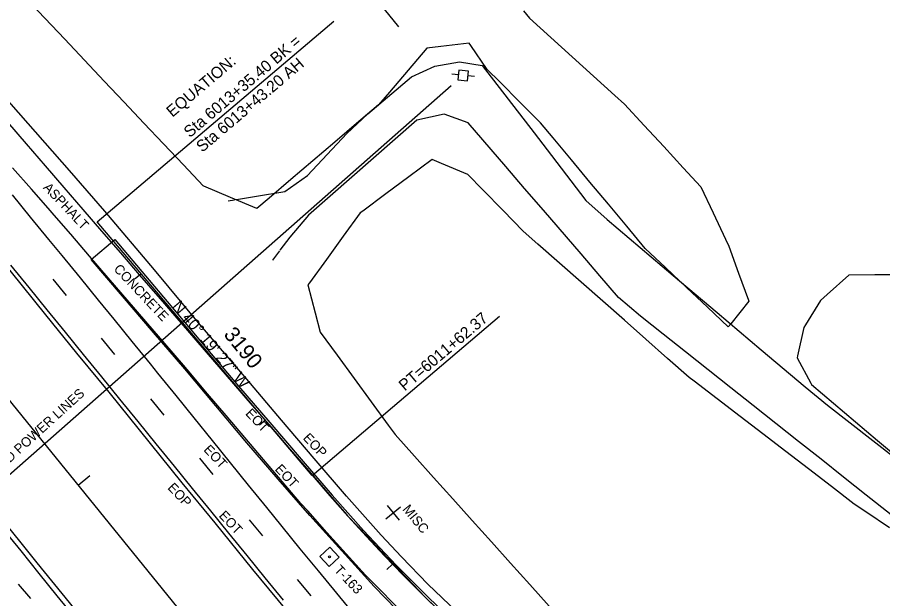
# Model space of a CAD drawing. Extents: x 2132221 to 2141942, y 535736 to 547298.
# Drawn here: x 2137049.2 to 2137499.9, y 541848.3 to 542151 of the extents above; entities that cross this region are included whole.
import ezdxf

# ---------------------------------------------------------------- set-up
doc = ezdxf.new("R2010")
doc.units = 0
for name, color, linetype in [('RD_EX_Conc', 7, 'Continuous'), ('RD_EX_Conc_txCode', 7, 'Continuous'), ('RD_EX_Driveway', 7, 'Continuous'), ('RD_EX_Fence_Other', 7, 'Continuous'), ('RD_EX_Misc', 7, 'Continuous'), ('RD_EX_Misc_txCode', 7, 'Continuous'), ('RD_EX_Road', 7, 'Continuous'), ('RD_EX_Road_txCode', 7, 'Continuous'), ('RD_EX_UT', 7, 'Continuous'), ('RD_EX_UT_txCode', 7, 'Continuous'), ('RD_EX_VEG', 7, 'Continuous'), ('RD_HC_Cl', 7, 'Continuous'), ('RD_HC_Data', 7, 'Continuous'), ('RD_HC_Data_Tic', 7, 'Continuous'), ('RD_HC_Survey', 7, 'Continuous'), ('RD_HC_Survey_txCode', 7, 'Continuous'), ('RD_HC_TX_Sta50', 7, 'Continuous')]:
    doc.layers.add(name, color=color, linetype=linetype)

msp = doc.modelspace()

# ---------------------------------------------------------------- linework, layer by layer
at = {"layer": 'RD_EX_Conc'}
for points in [[(2137218.21, 541873.14), (2137201.44, 541891.65), (2137184.99, 541910.51), (2137168.74, 541929.5), (2137152.52, 541948.71), (2137136.39, 541967.92), (2137120.09, 541986.91), (2137103.91, 542005.79), (2137087.68, 542024.93), (2137099.97, 542035.22)], [(2137099.97, 542035.22), (2137115.93, 542016.38), (2137131.94, 541997.4), (2137148.3, 541978.08), (2137164.43, 541958.88), (2137180.71, 541940), (2137196.93, 541920.84), (2137213.09, 541902.09), (2137229.51, 541883.81)], [(2137229.51, 541883.81), (2137246.53, 541865.74), (2137263.7, 541848.48), (2137281.3, 541831.66), (2137299.96, 541814.99), (2137318.59, 541798.76), (2137337.09, 541783.05), (2137356.44, 541767.8), (2137376, 541753.25), (2137396.14, 541739.29), (2137417.1, 541725.53), (2137433.69, 541715.25), (2137450.59, 541705.08), (2137467.05, 541695.39), (2137488.83, 541683.3), (2137510.4, 541672.14)], [(2137218.21, 541873.14), (2137235.03, 541854.67), (2137252.46, 541836.78), (2137270.68, 541819.74), (2137289.32, 541803.1), (2137308.09, 541786.67), (2137327.25, 541770.6), (2137346.9, 541755.12), (2137366.88, 541740.22), (2137387.48, 541725.85), (2137408.38, 541712.12), (2137425.24, 541701.55), (2137459.18, 541681.45), (2137481.25, 541669.35), (2137503.5, 541657.89)]]:
    msp.add_lwpolyline(points, dxfattribs=at)
at = {"layer": 'RD_EX_Driveway'}
msp.add_line((2137158.98, 542055.39), (2137162.25, 542055.93), dxfattribs=at)
for points in [[(2137163.24, 542056.1), (2137173.77, 542057.87), (2137188.56, 542060.36), (2137200.26, 542068.61), (2137210.52, 542079.55), (2137220.79, 542090.49), (2137231.68, 542100.7), (2137254.43, 542119.99), (2137266.64, 542125.59), (2137279.53, 542127.81), (2137291.29, 542125.97), (2137318.31, 542090.83), (2137327.31, 542079.11), (2137345.32, 542055.68), (2137356.39, 542045.68), (2137379.3, 542026.32), (2137390.75, 542016.63), (2137413.66, 541997.27), (2137425.11, 541987.59), (2137436.56, 541977.9), (2137459.47, 541958.54), (2137471.13, 541949.11), (2137482.96, 541939.89), (2137494.78, 541930.66), (2137506.6, 541921.43)], [(2137514.79, 541883.6), (2137491.27, 541902.22), (2137479.52, 541911.54), (2137467.76, 541920.85), (2137456, 541930.16), (2137444.24, 541939.48), (2137432.48, 541948.79), (2137420.72, 541958.1), (2137408.96, 541967.42), (2137397.2, 541976.73), (2137385.45, 541986.04), (2137373.69, 541995.35), (2137362.33, 542005.09), (2137352.54, 542016.45), (2137342.75, 542027.82), (2137323.18, 542050.55), (2137313.39, 542061.92), (2137303.6, 542073.28), (2137284.02, 542096.01), (2137271.52, 542100.49), (2137257.25, 542097.39), (2137245.98, 542087.5), (2137234.71, 542077.6), (2137223.44, 542067.71), (2137212.16, 542057.81), (2137200.89, 542047.92), (2137191.17, 542036.58), (2137185.96, 542029.7)], [(2137185.67, 542029.31), (2137182.12, 542024.62), (2137182.01, 542024.47)]]:
    msp.add_lwpolyline(points, dxfattribs=at)
at = {"layer": 'RD_EX_Fence_Other'}
msp.add_lwpolyline([(2137247.87, 542146.11), (2137182.09, 542227.22), (2137122.41, 542300.31), (2137065.86, 542367.6), (2136999.43, 542448.64), (2136994.13, 542440.26), (2136978.31, 542382.26), (2136963.2, 542329.45), (2136923.95, 542376.23), (2136870.08, 542440.87)], dxfattribs=at)
at = {"layer": 'RD_EX_Misc'}
for p, q in [((2137067.64, 542014.63), (2137074.65, 542006.18)), ((2137092.81, 541983.93), (2137099.83, 541975.48)), ((2137118.51, 541952.36), (2137125.53, 541943.91)), ((2137144.02, 541921.39), (2137151.04, 541912.94)), ((2137241.02, 541889.82), (2137248.76, 541896.15)), ((2137241.72, 541896.86), (2137248.05, 541889.12)), ((2137169.88, 541889.4), (2137176.9, 541880.95)), ((2137194.97, 541858.26), (2137201.99, 541849.81)), ((2137049.68, 541855.88), (2137055.97, 541848.35))]:
    msp.add_line(p, q, dxfattribs=at)
for points in [[(2137043.99, 542096.38), (2137053.8, 542085.03), (2137063.61, 542073.69), (2137073.43, 542062.34), (2137083.24, 542051), (2137093.05, 542039.65), (2137102.86, 542028.3), (2137112.67, 542016.96), (2137122.49, 542005.61), (2137132.3, 541994.27), (2137142.11, 541982.92), (2137151.92, 541971.58), (2137161.73, 541960.23), (2137171.55, 541948.88), (2137181.36, 541937.54), (2137191.17, 541926.19), (2137200.98, 541914.85), (2137210.79, 541903.5), (2137220.61, 541892.16), (2137221.17, 541891.5), (2137231.51, 541880.63), (2137241.85, 541869.76), (2137252.19, 541858.89), (2137261.52, 541849.09), (2137272.33, 541838.69)], [(2137246.83, 541844.11), (2137236.22, 541854.71), (2137230.47, 541860.45), (2137220.46, 541871.61), (2137210.44, 541882.78), (2137200.42, 541893.94), (2137196.89, 541897.88), (2137187.17, 541909.31), (2137177.45, 541920.74), (2137167.74, 541932.17), (2137158.02, 541943.59), (2137148.3, 541955.02), (2137138.59, 541966.45), (2137135.7, 541969.85), (2137125.91, 541981.21), (2137116.12, 541992.58), (2137106.33, 542003.95), (2137096.54, 542015.31), (2137086.75, 542026.68), (2137076.97, 542038.04), (2137067.18, 542049.41), (2137066.5, 542050.2), (2137056.54, 542061.42), (2137046.59, 542072.64)], [(2137046.42, 542058.6), (2137055.92, 542046.99), (2137065.42, 542035.38), (2137072.35, 542026.91), (2137081.85, 542015.3), (2137091.35, 542003.69), (2137099.42, 541993.84), (2137108.86, 541982.18), (2137118.31, 541970.53), (2137122.24, 541965.68), (2137131.69, 541954.02), (2137141.13, 541942.37), (2137150.58, 541930.72), (2137160.02, 541919.06), (2137169.47, 541907.41), (2137178.91, 541895.76), (2137186.89, 541885.92), (2137196.38, 541874.31), (2137205.88, 541862.7), (2137215.38, 541851.09), (2137224.87, 541839.48)], [(2137045.61, 542021.99), (2137055.08, 542010.35), (2137064.54, 541998.72), (2137074.01, 541987.08), (2137083.47, 541975.44), (2137092.94, 541963.81), (2137102.4, 541952.17), (2137111.87, 541940.53), (2137121.33, 541928.9), (2137130.8, 541917.26), (2137140.26, 541905.62), (2137149.73, 541893.98), (2137159.19, 541882.35), (2137168.66, 541870.71), (2137178.12, 541859.07), (2137187.59, 541847.44)], [(2137041.5, 541884.78), (2137050.93, 541873.11), (2137060.37, 541861.45), (2137069.8, 541849.79), (2137079.24, 541838.13)]]:
    msp.add_lwpolyline(points, dxfattribs=at)
at = {"layer": 'RD_EX_Road'}
for points in [[(2136707.76, 542424.02), (2136729, 542399.05), (2136756.88, 542366.08), (2136784.05, 542334.02), (2136809.93, 542303.58), (2136839.08, 542269.1), (2136860.77, 542243.12), (2136882.71, 542216.67), (2136907.37, 542186.91), (2136924.47, 542166.25), (2136945.23, 542140.83), (2136969.19, 542111.86), (2136995.45, 542079.97), (2137017.76, 542052.48), (2137039.43, 542026.33), (2137063.92, 541996), (2137080.05, 541976.19), (2137096.8, 541955.76), (2137112.6, 541936.21), (2137134.84, 541908.64), (2137151.98, 541887.74), (2137171.65, 541863.54), (2137193.35, 541837.19)], [(2137129.75, 541780.57), (2137107.7, 541807.88), (2137088.48, 541831.26), (2137076.31, 541846.31), (2137059.57, 541866.89), (2137038.31, 541893.09), (2137028.99, 541904.49), (2137023.6, 541911.43), (2137008.32, 541930.08), (2136988.29, 541954.48), (2136973.96, 541972.2), (2136960.6, 541988.74), (2136942.64, 542011.01), (2136927.03, 542029.72), (2136910.37, 542050.05), (2136891.8, 542072.92), (2136874.04, 542094.49), (2136856.69, 542115.76), (2136841.62, 542134.18), (2136823.08, 542157.17)], [(2137238.6, 541881.27), (2137220.69, 541901.6), (2137203.74, 541921.2), (2137186.82, 541941.2), (2137168.67, 541962.64), (2137143.61, 541991.98), (2137120.53, 542019.5), (2137094.83, 542050.1), (2137076.39, 542071.19), (2137054.83, 542095.62), (2137026.8, 542127.26), (2137018.27, 542136.37), (2137005.48, 542151.45)], [(2137238.6, 541881.27), (2137249.22, 541870), (2137262.96, 541855.81), (2137277.81, 541841.67), (2137299.01, 541821.8), (2137319.34, 541804.37), (2137349.76, 541779.52), (2137377.32, 541758.51), (2137405.41, 541739.28), (2137439.15, 541717.58), (2137454.77, 541707.85), (2137477.42, 541694.77), (2137496.58, 541684.57), (2137514.52, 541675.68)]]:
    msp.add_lwpolyline(points, dxfattribs=at)
at = {"layer": 'RD_EX_UT'}
for p, q in [((2137279.18, 542123.38), (2137278.67, 542118.41)), ((2137284.15, 542122.87), (2137279.18, 542123.38)), ((2137279, 542120.95), (2137275.38, 542121.33)), ((2137283.64, 542117.9), (2137284.15, 542122.87)), ((2137287.32, 542120.09), (2137283.86, 542120.45)), ((2136830.18, 541723.72), (2137275.07, 542115.4)), ((2137278.67, 542118.41), (2137283.64, 542117.9))]:
    msp.add_line(p, q, dxfattribs=at)
at = {"layer": 'RD_EX_VEG'}
for points in [[(2137312.78, 542154.31), (2137315.9, 542150.61), (2137327.01, 542140.54), (2137338.13, 542130.47), (2137349.24, 542120.4), (2137360.36, 542110.32), (2137365.44, 542105.72), (2137375.62, 542094.7), (2137385.8, 542083.68), (2137395.97, 542072.66), (2137405.17, 542062.7), (2137411.55, 542049.12), (2137417.92, 542035.54), (2137419.66, 542031.83), (2137424.8, 542017.74), (2137429.95, 542003.65), (2137430.15, 542003.11), (2137420.78, 541991.39), (2137419.46, 541989.74), (2137408.56, 542000.05), (2137397.66, 542010.35), (2137386.75, 542020.65), (2137376.19, 542030.63), (2137366.6, 542042.16), (2137357, 542053.69), (2137347.41, 542065.22), (2137337.81, 542076.75), (2137328.22, 542088.28), (2137321.71, 542096.1), (2137311.1, 542106.71), (2137300.5, 542117.32), (2137293.93, 542123.89), (2137285.44, 542136.26), (2137284.58, 542137.52), (2137269.69, 542135.72), (2137262.41, 542134.84), (2137252.67, 542123.44), (2137242.93, 542112.03), (2137237.3, 542105.45), (2137225.89, 542095.72), (2137214.48, 542085.98), (2137203.07, 542076.24), (2137191.66, 542066.51), (2137180.25, 542056.77), (2137173.99, 542051.44), (2137160.17, 542057.25), (2137146.34, 542063.07), (2137145.96, 542063.23), (2137135.66, 542074.14), (2137125.36, 542085.04), (2137115.06, 542095.95), (2137104.77, 542106.86), (2137094.47, 542117.76), (2137084.17, 542128.67), (2137073.87, 542139.57), (2137063.57, 542150.48), (2137053.28, 542161.39)], [(2137503.44, 541885.18), (2137491, 541893.56), (2137485.07, 541897.56), (2137473.16, 541906.69), (2137461.26, 541915.81), (2137449.36, 541924.94), (2137437.45, 541934.07), (2137425.55, 541943.19), (2137413.64, 541952.32), (2137401.74, 541961.45), (2137399.07, 541963.5), (2137387.81, 541973.42), (2137376.56, 541983.33), (2137365.31, 541993.25), (2137354.06, 542003.17), (2137342.8, 542013.09), (2137331.55, 542023.01), (2137320.3, 542032.93), (2137312.59, 542039.72), (2137302.12, 542050.46), (2137291.64, 542061.19), (2137283.86, 542069.17), (2137270.01, 542074.91), (2137265.17, 542076.91), (2137253.13, 542067.97), (2137241.09, 542059.02), (2137229.05, 542050.07), (2137227.78, 542049.12), (2137218.94, 542037), (2137210.11, 542024.87), (2137201.28, 542012.75), (2137200.53, 542011.71), (2137204.32, 541997.2), (2137206.94, 541987.13), (2137215.78, 541975.01), (2137224.62, 541962.89), (2137233.47, 541950.78), (2137242.31, 541938.66), (2137245.94, 541933.69), (2137255.96, 541922.53), (2137265.99, 541911.37), (2137276.02, 541900.22), (2137286.05, 541889.06), (2137296.07, 541877.91), (2137306.1, 541866.75), (2137316.13, 541855.59), (2137326.16, 541844.44)], [(2137510.8, 542016.96), (2137495.8, 542016.82), (2137482.23, 542016.69), (2137471.03, 542006.71), (2137467.53, 542003.59), (2137459.61, 541990.86), (2137458.72, 541989.43), (2137455.49, 541974.78), (2137455.25, 541973.67), (2137462.39, 541960.47), (2137462.78, 541959.75), (2137474.23, 541950.07), (2137485.69, 541940.39), (2137497.15, 541930.71), (2137508.61, 541921.03)]]:
    msp.add_lwpolyline(points, dxfattribs=at)
at = {"layer": 'RD_HC_Cl'}
for p, q in [((2137202.7, 541912.5), (2137090.72, 542044.42)), ((2136971.61, 542041.65), (2141699.63, 536226.46))]:
    msp.add_line(p, q, dxfattribs=at)
for centre, radius, start, end in [((2135716.74, 541144.04), 1431.84, 1.67918, 36.06251), ((2137944.04, 542541.74), 972.38, 220.32405, 325.12405), ((2135784.3, 541107.9), 1400.95, 1.32972, 36.48455)]:
    msp.add_arc(centre, radius, start, end, dxfattribs=at)
at = {"layer": 'RD_HC_Data'}
for p, q in [((2137090.72, 542044.42), (2137213.96, 542149.03)), ((2137202.7, 541912.5), (2137300.36, 541995.4))]:
    msp.add_line(p, q, dxfattribs=at)
at = {"layer": 'RD_HC_Data_Tic'}
for p, q in [((2137113.63, 542017.44), (2137110.58, 542014.85)), ((2137178.34, 541941.2), (2137175.29, 541938.61)), ((2137080.77, 541907.39), (2137086.98, 541912.44)), ((2137244.55, 541866.28), (2137241.67, 541863.51))]:
    msp.add_line(p, q, dxfattribs=at)
at = {"layer": 'RD_HC_Survey'}
msp.add_lwpolyline([(2137216.79, 541869.89), (2137211.94, 541875.04), (2137206.79, 541870.19), (2137211.64, 541865.04)], close=True, dxfattribs=at)
msp.add_circle((2137211.79, 541870.04), 0.5, dxfattribs=at)

# ---------------------------------------------------------------- texts
at = {"layer": 'RD_EX_Conc_txCode'}
msp.add_text('CONCRETE', height=5, rotation=313.3162, dxfattribs=at).set_placement((2137099.04, 542019.65))
at = {"layer": 'RD_EX_Misc_txCode'}
for s, rotation, p in [('EOT', 313.3162, (2137167.62, 541944.43)), ('EOT', 313.3162, (2137145.86, 541925.57)), ('EOT', 313.3162, (2137183.01, 541915.46)), ('EOT', 313.3162, (2137153.82, 541891.24)), (' MISC', 309.2571, (2137248.32, 541896.15))]:
    msp.add_text(s, height=5, rotation=rotation, dxfattribs=at).set_placement(p)
at = {"layer": 'RD_EX_Road_txCode'}
for s, p in [('ASPHALT', (2137062.33, 542062.06)), ('EOP', (2137197.61, 541931.65)), ('EOP', (2137127.1, 541905.78))]:
    msp.add_text(s, height=5, rotation=313.3162, dxfattribs=at).set_placement(p)
at = {"layer": 'RD_EX_UT_txCode'}
msp.add_text('OVHD POWER LINES', height=5, rotation=42.2008, dxfattribs=at).set_placement((2137034.54, 541909.11))
at = {"layer": 'RD_HC_Data'}
for s, rotation, p in [('Sta 6013+35.40 BK = ', 40.3241, (2137138.99, 542088.01)), ('EQUATION:', 40.3241, (2137129.93, 542098.68)), ('Sta 6013+43.20 AH', 40.3241, (2137145.46, 542080.39)), ('N 40%%d 19\' 27" W', 310.3241, (2137129.45, 542000.34)), ('PT=6011+62.37', 40.3241, (2137250.96, 541956.09))]:
    msp.add_text(s, height=6, rotation=rotation, dxfattribs=at).set_placement(p)
at = {"layer": 'RD_HC_Survey_txCode'}
msp.add_text('T-163', height=5, rotation=313.3396, dxfattribs=at).set_placement((2137213.86, 541862.93))
at = {"layer": 'RD_HC_TX_Sta50'}
msp.add_text('3190', height=8, rotation=309.1127, dxfattribs=at).set_placement((2137156.27, 541985.73))

doc.saveas('drawing.dxf')
